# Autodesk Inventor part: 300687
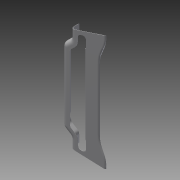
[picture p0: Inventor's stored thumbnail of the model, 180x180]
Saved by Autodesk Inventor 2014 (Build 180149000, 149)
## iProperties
Created: 2007-11
Part Number: 300687
Document SubType Name: Modeling
Designer: MM
Density: 7.85 g/cm^3
Mass: 235.532 g
Surface Area: 616.109 cm^2
Volume: 30.0041 cm^3
Material: Steel
Description: BACK TOP PLATE
Appearance: Steel
Component Category: Back Component
Author: MM
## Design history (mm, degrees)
sketch "Sketch1"
  geometry: L1 (0, 25.158)-(0, 0); L2 (105.616, 18.019)-(0, 0); L3 (0, 25.158)-(101.445, 42.466); L4 (101.445, 42.466)-(105.616, 18.019); L5 (0, 50.959)-(0, -8.493) reference; L6 (-21.123, 0)-(126.739, 0) reference; 1 further point
  constraints: 8 end point, 1 coincident, 1 collinear, 1 parallel, 1 perpendicular
  dimensions: "d1" = 80.3179 deg angle of L2 L1; "d2" = 24.79998 distance between parallel lines of L3 L2; "d4" = 102.91071 distance of L1.start L3.end (derived); "d15" = 18.01935 distance from line of L6 L2.start
extrude "Extrusion1" new body sketch "Sketch1" stored distance "d5" = 326; taper "d6" = 0 deg
sketch "Sketch2"
  geometry: L1 (-19.437, -118.02)-(0, -100.911); L2 (-19.437, -144.682)-(-19.437, -118.02); L3 (0, -163)-(0, 163) reference; L4 (-105.616, -163)-(0, -163); L5 (0, -163)-(0, -100.911); L6 (-105.616, -163)-(-105.616, 163) reference; L7 (-105.616, -163)-(-19.437, -144.682); 3 further points; 1 other entity
  constraints: 10 end point, 3 point on line, 1 horizontal, 2 other
  dimensions: "d7" = 19.43721 distance between parallel lines of L2 L3; "d8" = 118.01969 vertical distance of point (0, 0) L1.start; "d9" = 100.91084 distance of point (0, 0) L1.end; "d12" = 78 deg angle of L7 L2
extrude "Extrusion2" cut sketch "Sketch2" stored distance "d10" = 341; taper "d11" = 0 deg
mirror "Mirror1"
fillet "Fillet1" dims "d13" = 15, "d14" = 12
sketch "Sketch3"
  geometry: L1 (0, 0)-(0, 326) reference; L2 (-15.5, 60.5)-(-15.5, 265.5); L3 (0, 21)-(-15.5, 60.5); L4 (-15.5, 265.5)-(0, 305); L5 (-129.393, 163)-(26.362, 163) reference; 2 further points
  constraints: 6 end point, 3 point on line, 1 midpoint
  dimensions: "d16" = 15.5 distance between parallel lines of L1 L2; "d17" = 205 distance of L2.start L2.end; "d18" = 142 distance from line of L5 L3.start; "d19" = 142 distance from line of L4.end L5 (= d18)
extrude "Extrusion3" cut sketch "Sketch3" stored distance "d20" = 341; taper "d21" = 0 deg
fillet "Fillet2" dims "d22" = 90, "d23" = 5
shell "Shell1" dims "d24" = 1
sketch "Sketch4"
  geometry: L1 (88.492, 17.637)-(109.385, 21.201); L2 (109.385, 21.201)-(103.667, 54.717); L3 (103.667, 54.717)-(20.437, 40.517); L4 (85.24, 15.557)-(33.287, 6.694); L5 (20.437, 17.537)-(20.437, 40.517); L6 (19.437, 17.537)-(19.437, 28.475) reference; 2 further points
  constraints: 10 end point, 2 perpendicular, 3 other
  dimensions: "d26" = 34 distance of L1.end L2.end; "d34" = 99.6821 deg angle of L3 L5; "d36" = 40.51701 vertical distance of point (0, 0) L3.end; "d37" = 109.38541 horizontal distance of point (0, 0) L1.end; "d38" = 180 deg angle of L6 L5
extrude "Extrusion4" cut sketch "Sketch4" stored distance "d27" = 341; taper "d28" = 0 deg
sketch "Sketch11"
  geometry: L1 (19.458, 1.504)-(3.622, 1.504) reference; L2 (0, 0)-(15.837, 0) reference; L3 (0, 0)-(0, 1.504); L4 (19.458, 1.504)-(0, 1.504); 1 further point
  constraints: 4 end point, 1 collinear, 1 perpendicular, 1 other
sketch "Sketch12"
  geometry: L1 (-65.362, 311.946)-(-49.825, 318.756) reference; L2 (-50.648, 317.303)-(-65.152, 310.946) reference; 2 further points
  constraints: 4 other
sweep "Sweep2" sketch "Sketch11", "Sketch12" dims "d39" = 0
mirror "Mirror3"
sketch "Sketch13"
  geometry: C1 r 11.5 at (179.131, 18.975); C2 r 11.5 at (9.131, 18.975); 1 further point
  constraints: 2 centre point
  dimensions: "d40" = 23 diameter of C2; "d41" = 23 diameter of C1; "d42" = 33.19614 vertical distance of C2.centre point (94.131, -14.221); "d43" = 170 distance of C1.centre C2.centre; "d44" = 85 horizontal distance of point (94.131, -14.221) C1.centre; "d45" = 33.19614 vertical distance of C1.centre point (94.131, -14.221)
extrude "Extrusion7" cut sketch "Sketch13" distance "d46" = 5; taper "d47" = 0 deg
sketch "Sketch14"
  geometry: L1 (87.921, 256.083)-(19.718, 241.793) reference; L2 (19.718, 218.931)-(19.718, 241.793) reference; L3 (1.033, 190.514)-(10.425, 198.663) reference; L4 (0, 0)-(0, 188.262) reference; L5 (10.425, -10.402)-(1.033, -2.252) reference; L6 (19.718, -53.531)-(19.718, -30.669) reference; L7 (19.718, -53.531)-(87.921, -67.821) reference; L8 (5, 0.925)-(13.702, -6.625); L9 (24.718, -30.669)-(24.718, -44.361); L10 (24.718, -44.361)-(45, -48.611); L11 (5, 0.925)-(5, 187.336); L12 (45, 236.873)-(24.718, 232.623); L13 (24.718, 232.623)-(24.718, 218.931); L14 (13.702, 194.887)-(5, 187.336); L15 (45, -48.611)-(45, 236.873); 1 further point
  constraints: 16 end point, 4 parallel, 8 other
  dimensions: "d48" = 5 distance between parallel lines of L5 L8; "d49" = 5 distance between parallel lines of L4 L11 (= d48); "d50" = 5 distance between parallel lines of L3 L14 (= d48); "d51" = 40 distance between parallel lines of L15 L11; "d52" = 5 distance between parallel lines of L2 L13 (= d48); "d53" = 5 distance between parallel lines of L6 L9 (= d48); "d54" = 10 distance between parallel lines of L7 L10; "d55" = 10 distance between parallel lines of L1 L12 (= d54)
extrude "Extrusion8" cut sketch "Sketch14" distance "d56" = 1; taper "d57" = 0 deg
fillet "Fillet3" dims "d58" = 8
sketch "Sketch16"
  geometry: L1 (54.341, 52.267)-(54.341, 9.271); L2 (1, 25.329)-(1, 14.221) reference; L3 (13.85, 3.377)-(18.779, 4.218) reference; L4 (18.779, 4.218)-(18.947, 3.233) reference; L5 (18.947, 3.233)-(14.018, 2.392) reference; L6 (0, 14.221)-(0, 25.158) reference; L7 (0, 25.158)-(1, 25.329) reference; L8 (88.492, 17.637)-(89.579, 17.822) reference; L9 (85.408, 14.572)-(58.377, 9.96) reference; L10 (58.377, 9.96)-(58.209, 10.946) reference; L11 (58.209, 10.946)-(85.24, 15.557) reference; L12 (58.209, 10.946)-(55.341, 10.456); L13 (58.377, 9.96)-(54.341, 9.271); L14 (55.341, 10.456)-(55.341, 52.438); L15 (58.209, 10.946)-(58.377, 9.96); L16 (55.341, 52.438)-(54.341, 52.267); 1 further point
  constraints: 12 end point, 3 parallel, 1 collinear, 1 perpendicular, 4 other
  dimensions: "d60" = 1 distance between parallel lines of L14 L1; "d61" = 42.99584 distance of L1.start L1.end
extrude "Extrusion9" join sketch "Sketch16" stored distance "d62" = 220; taper "d63" = 0 deg
fillet "Fillet4" dims "d64" = 2.25
fillet "Fillet5" dims "d65" = 3.25
fillet "Fillet6" dims "d66" = 2.25
sketch "Sketch17"
  geometry: L1 (220, 0)-(0, 0) reference; L2 (0, 0)-(0, -39.144) reference; L3 (155, -20)-(65, -20); L4 (65, -20)-(41.165, 0); L5 (155, -20)-(178.835, 0); L6 (110, -20)-(110, 0); L7 (220, -39.144)-(220, 0) reference; L8 (178.835, 0)-(184.794, 5); L9 (184.794, 5)-(35.206, 5); L10 (41.165, 0)-(35.206, 5); 1 further point
  constraints: 14 end point, 3 perpendicular, 2 collinear, 2 midpoint, 2 point on line
  dimensions: "d67" = 20 distance between parallel lines of L1 L3; "d68" = 40 deg angle of L5 L3; "d69" = 40 deg angle of L4 L3; "d70" = 90 distance of L3.start L3.end; "d73" = 5 distance between parallel lines of L9 L1
extrude "Extrusion10" cut sketch "Sketch17" distance "d71" = 1; taper "d72" = 0 deg
fillet "Fillet7" dims "d74" = 12
sketch "Sketch18"
  geometry: L1 (36.594, 39.144)-(12, 39.144) reference; L2 (195, 23.066)-(25, 23.066); C1 r 9 at (195, 23.066); C2 r 9 at (25, 23.066); 1 further point
  constraints: 2 centre point, 2 end point, 1 parallel
  dimensions: "d77" = 36.18824 distance from line of point (110, -13.123) L2; "d78" = 169.99945 distance of L2.start L2.end; "d79" = 84.99973 horizontal distance of point (110, -13.123) L2.end; "d80" = 18 diameter of C2; "d81" = 18 diameter of C1 (= d80)
extrude "Extrusion11" cut sketch "Sketch18" distance "d75" = 1; taper "d76" = 0 deg
sketch "Sketch19"
  geometry: L1 (36.594, 39.144)-(12, 39.144) reference; L2 (163.5, 18.511)-(56.5, 18.511); L3 (110, 52.58)-(110, -24.073) reference; 1 further point
  constraints: 2 end point, 1 parallel
  dimensions: "d82" = 107 distance of L2.start L2.end; "d83" = 53.5 distance from line of L3 L2.start (= 0.5 x d82); "d84" = 31.63328 distance from line of point (110, -13.123) L2
hole "Hole1" sketch "Sketch19" at (163.5, 18.511), (56.5, 18.511) diameter "d85" = 6; stored, may be unused: countersink angle "d89" = 90 deg, drill point angle "d91" = 118 deg; dims "d86" = 6, "d87" = 4, "d88" = 2, "d90" = 8
body "Solid1"
node "Project Cut Edges3"
